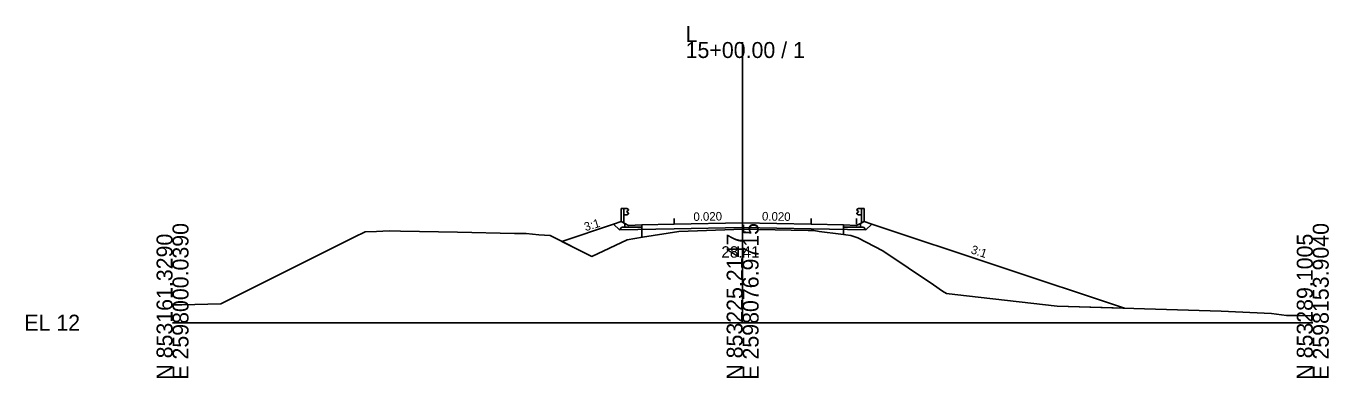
# Model space of a CAD drawing. Extents: x -26 to 1203, y -10 to 9526.
# Drawn here: x -25.7 to 202.8, y 4990.3 to 5052 of the extents above; entities that cross this region are included whole.
import ezdxf

# ---------------------------------------------------------------- set-up
doc = ezdxf.new("R2010")
doc.units = 0
for name, color, linetype in [('Default', 7, 'Continuous'), ('Exist Cross Section Cell', 7, 'Continuous'), ('Exist XS Center Line Elevation Label', 7, 'Continuous'), ('Exist XS Ground Line', 7, 'Continuous'), ('Prop XS Earthwork Shape', 7, 'Continuous'), ('Prop XS EOT Tick Mark', 7, 'Continuous'), ('Prop XS Finish Grade', 7, 'Continuous'), ('Prop XS Finish Grade Earthwork', 7, 'Continuous'), ('Prop XS Finish Grade Paved Shoulder', 7, 'Continuous'), ('Prop XS Finish Grade Pavement', 7, 'Continuous'), ('Prop XS Guardrail', 7, 'Continuous'), ('Prop XS Pvmt Edge Slope', 7, 'Continuous'), ('Prop XS SBG', 7, 'Continuous'), ('Prop XS SE Text', 7, 'Continuous'), ('Prop XS Side Slope Text', 7, 'Continuous'), ('Prop XS Subgrade Earthwork', 7, 'Continuous'), ('Scratch_Level_5', 7, 'Continuous')]:
    doc.layers.add(name, color=color, linetype=linetype)

msp = doc.modelspace()

# ---------------------------------------------------------------- linework, layer by layer
at = {"layer": 'Default'}
msp.add_line((120, 5017.27), (120, 5018.27), dxfattribs=at)
at = {"layer": 'Exist Cross Section Cell'}
for p, q in [((100, 5000), (100, 5049.23)), ((0, 5000), (100, 5000)), ((100, 5000), (200, 5000))]:
    msp.add_line(p, q, dxfattribs=at)
at = {"layer": 'Exist XS Ground Line'}
for p, q in [((92.11, 5016.14), (100.05, 5016.41)), ((100.05, 5016.41), (108.51, 5016.24)), ((8.49, 5003.29), (31.88, 5014.99)), ((31.88, 5014.99), (33.76, 5015.93)), ((33.76, 5015.93), (35.76, 5016.01)), ((35.76, 5016.01), (38, 5016.1)), ((38, 5016.1), (40, 5016.06)), ((40, 5016.06), (50, 5015.86)), ((50, 5015.86), (60, 5015.66)), ((60, 5015.66), (62, 5015.62)), ((62, 5015.62), (64.23, 5015.44)), ((64.23, 5015.44), (66.23, 5015.28)), ((66.23, 5015.28), (73.56, 5011.62)), ((73.56, 5011.62), (79.74, 5014.55)), ((79.74, 5014.55), (82.42, 5014.99)), ((82.42, 5014.99), (88.81, 5016.02)), ((88.81, 5016.02), (92.11, 5016.14)), ((108.51, 5016.24), (111.49, 5016.18)), ((111.49, 5016.18), (112.51, 5016.15)), ((112.51, 5016.15), (113.42, 5016.02)), ((113.42, 5016.02), (117.21, 5015.55)), ((117.21, 5015.55), (118.98, 5015.3)), ((118.98, 5015.3), (120.22, 5014.91)), ((120.22, 5014.91), (123.15, 5013.37)), ((123.15, 5013.37), (124.59, 5012.63)), ((124.59, 5012.63), (133.48, 5006.62)), ((133.48, 5006.62), (135.03, 5005.51)), ((135.03, 5005.51), (135.76, 5005.1)), ((135.76, 5005.1), (137.2, 5004.94)), ((137.2, 5004.94), (155.17, 5002.89)), ((0, 5003.15), (1.64, 5003.16)), ((1.64, 5003.16), (8.49, 5003.29)), ((155.17, 5002.89), (183.94, 5002)), ((183.94, 5002), (192.74, 5001.64)), ((192.74, 5001.64), (194.5, 5001.37)), ((194.5, 5001.37), (195.37, 5001.27)), ((195.37, 5001.27), (197.31, 5001.25)), ((197.31, 5001.25), (199.42, 5001.22)), ((199.42, 5001.22), (200, 5001.26))]:
    msp.add_line(p, q, dxfattribs=at)
at = {"layer": 'Prop XS Earthwork Shape'}
msp.add_lwpolyline([(112, 5016.48), (121.62, 5016.29), (122.64, 5017.3), (166.98, 5002.52), (155.17, 5002.89), (137.2, 5004.94), (135.76, 5005.1), (135.03, 5005.51), (133.48, 5006.62), (124.59, 5012.63), (123.15, 5013.37), (120.22, 5014.91), (118.98, 5015.3), (117.21, 5015.55), (113.42, 5016.02), (112.51, 5016.15), (111.49, 5016.18), (108.51, 5016.24), (100.05, 5016.41), (92.11, 5016.14), (88.81, 5016.02), (82.42, 5014.99), (79.74, 5014.55), (73.56, 5011.62), (68.26, 5014.27), (77.36, 5017.3), (78.38, 5016.29), (88, 5016.48), (100, 5016.72)], close=True, dxfattribs=at)
at = {"layer": 'Prop XS EOT Tick Mark'}
for p, q in [((88, 5017.27), (88, 5018.27)), ((112, 5017.27), (112, 5018.27))]:
    msp.add_line(p, q, dxfattribs=at)
at = {"layer": 'Prop XS Finish Grade'}
for p, q in [((78.67, 5017.74), (77.36, 5017.3)), ((79.33, 5017.41), (78.69, 5017.73)), ((120.67, 5017.41), (121.31, 5017.73)), ((121.33, 5017.74), (122.64, 5017.3))]:
    msp.add_line(p, q, dxfattribs=at)
at = {"layer": 'Prop XS Finish Grade Earthwork'}
for p, q in [((77.36, 5017.3), (68.26, 5014.27)), ((122.64, 5017.3), (166.98, 5002.52))]:
    msp.add_line(p, q, dxfattribs=at)
at = {"layer": 'Prop XS Finish Grade Paved Shoulder'}
for p, q in [((88, 5017.27), (82.33, 5017.16)), ((112, 5017.27), (117.67, 5017.16))]:
    msp.add_line(p, q, dxfattribs=at)
at = {"layer": 'Prop XS Finish Grade Pavement'}
for p, q in [((88, 5017.27), (100, 5017.51)), ((100, 5017.51), (112, 5017.27))]:
    msp.add_line(p, q, dxfattribs=at)
at = {"layer": 'Prop XS Guardrail'}
for p, q in [((78.67, 5017.74), (78.67, 5020.03)), ((78.67, 5020.03), (79.17, 5020.03)), ((79.17, 5020.03), (79.17, 5017.49)), ((79.17, 5020.03), (79.67, 5020.03)), ((79.67, 5018.9), (79.17, 5018.9)), ((79.67, 5020.03), (79.96, 5019.83)), ((79.96, 5019.71), (79.67, 5019.51)), ((79.67, 5019.51), (79.67, 5019.42)), ((79.67, 5019.42), (79.96, 5019.22)), ((79.96, 5019.1), (79.67, 5018.9)), ((79.96, 5019.83), (79.99, 5019.77)), ((79.99, 5019.77), (79.96, 5019.71)), ((79.96, 5019.22), (79.99, 5019.16)), ((79.99, 5019.16), (79.96, 5019.1)), ((120.04, 5019.83), (120.01, 5019.77)), ((120.01, 5019.77), (120.04, 5019.71)), ((120.04, 5019.22), (120.01, 5019.16)), ((120.01, 5019.16), (120.04, 5019.1)), ((120.33, 5020.03), (120.04, 5019.83)), ((120.04, 5019.71), (120.33, 5019.51)), ((120.33, 5019.42), (120.04, 5019.22)), ((120.04, 5019.1), (120.33, 5018.9)), ((120.83, 5020.03), (120.33, 5020.03)), ((120.33, 5019.51), (120.33, 5019.42)), ((120.33, 5018.9), (120.83, 5018.9)), ((121.33, 5020.03), (120.83, 5020.03)), ((120.83, 5020.03), (120.83, 5017.49)), ((121.33, 5017.74), (121.33, 5020.03))]:
    msp.add_line(p, q, dxfattribs=at)
at = {"layer": 'Prop XS Pvmt Edge Slope'}
for p, q in [((78.83, 5016.74), (78.38, 5016.29)), ((78.83, 5016.74), (79.33, 5016.74)), ((120.67, 5016.74), (121.17, 5016.74)), ((121.17, 5016.74), (121.62, 5016.29))]:
    msp.add_line(p, q, dxfattribs=at)
at = {"layer": 'Prop XS SBG'}
for p, q in [((79.33, 5016.74), (79.33, 5017.41)), ((79.33, 5017.41), (80, 5017.07)), ((82.33, 5016.74), (79.33, 5016.74)), ((80, 5017.07), (82.33, 5017.16)), ((82.33, 5017.16), (82.33, 5016.74)), ((117.67, 5017.16), (117.67, 5016.74)), ((120, 5017.07), (117.67, 5017.16)), ((117.67, 5016.74), (120.67, 5016.74)), ((120.67, 5017.41), (120, 5017.07)), ((120.67, 5016.74), (120.67, 5017.41))]:
    msp.add_line(p, q, dxfattribs=at)
at = {"layer": 'Prop XS Subgrade Earthwork'}
for p, q in [((78.38, 5016.29), (77.36, 5017.3)), ((88, 5016.48), (78.38, 5016.29)), ((100, 5016.72), (88, 5016.48)), ((112, 5016.48), (100, 5016.72)), ((112, 5016.48), (121.62, 5016.29)), ((121.62, 5016.29), (122.64, 5017.3))]:
    msp.add_line(p, q, dxfattribs=at)
at = {"layer": 'Scratch_Level_5'}
for p, q in [((82.33, 5014.98), (82.33, 5017.16)), ((100, 5016.41), (100, 5017.51)), ((117.67, 5015.48), (117.67, 5017.16))]:
    msp.add_line(p, q, dxfattribs=at)

# ---------------------------------------------------------------- texts
at = {"layer": 'Exist Cross Section Cell'}
for s, p in [('L', (90, 5049.23)), ('15+00.00 / 1', (90, 5046.43)), ('EL 12', (-26, 4998.6))]:
    msp.add_text(s, height=2.8, dxfattribs=at).set_placement(p)
for s, p in [('E 2598000.0390', (2.8, 4990)), ('E 2598076.9715', (102.8, 4990)), ('E 2598153.9040', (202.8, 4990)), ('N 853161.3290', (0, 4990)), ('N 853225.2147', (100, 4990)), ('N 853289.1005', (200, 4990))]:
    msp.add_text(s, height=2.8, rotation=90, dxfattribs=at).set_placement(p)
at = {"layer": 'Exist XS Center Line Elevation Label'}
msp.add_text('28.41', height=2, dxfattribs=at).set_placement((96.27, 5011.41))
at = {"layer": 'Prop XS SE Text'}
for rotation, p in [(1.1458, (91.38, 5017.84)), (358.8542, (103.38, 5017.94))]:
    msp.add_text('0.020', height=1.5, rotation=rotation, dxfattribs=at).set_placement(p)
at = {"layer": 'Prop XS Side Slope Text'}
for rotation, p in [(16.5928, (72.44, 5016.04)), (341.5651, (139.91, 5012.21))]:
    msp.add_text('3:1', height=1.5, rotation=rotation, dxfattribs=at).set_placement(p)

doc.saveas('drawing.dxf')
